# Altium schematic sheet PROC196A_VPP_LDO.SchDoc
size 431 x 279 mm; Date: Not shown in title block; ApprovedBy: Not shown in title block; CheckedBy: Not shown in title block; Author: Not shown in title block; CompanyName: Not shown in title block; Engineer: Not shown in title block; Organization: Not shown in title block; Address1: Not shown in title block; Address2: Not shown in title block; Address3: Not shown in title block; Address4: Not shown in title block; DocumentNumber: 10; Revision: Use project parameter SCH_Rev; SheetNumber: 10; SheetTotal: 25; PageSetup: Record=PageOptions¦CenterHorizontal=True¦CenterVertical=True¦PrintScale=1.00¦XCorrection=1.00¦YCorrection=1.00¦PrintKind=0¦BorderSize=5000000¦LeftOffset=0¦BottomOffset=0¦Orientation=2¦PaperLength=1000¦PaperWidth=1000¦Scale=100¦PaperSource=15¦PrintQuality=600¦MediaType=1¦DitherType=10¦PaperKind=Letter¦PrintScaleMode=1
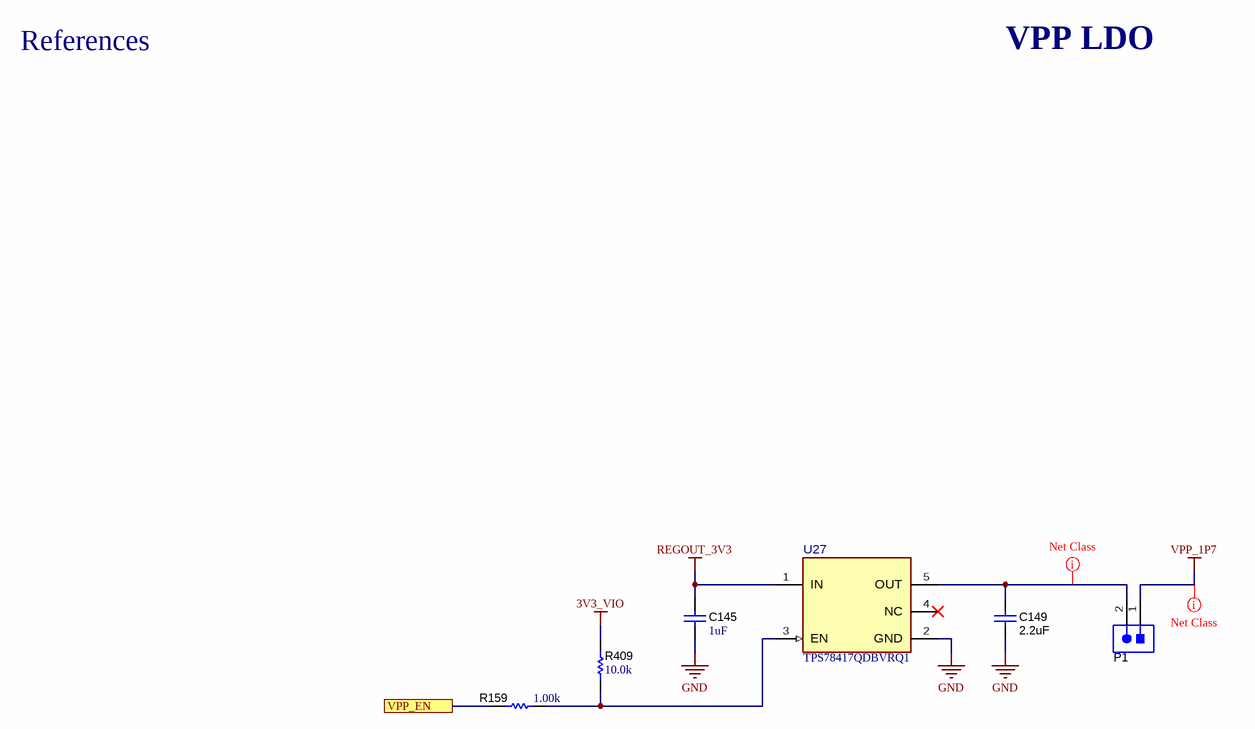
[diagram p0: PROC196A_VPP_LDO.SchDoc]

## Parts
C145  ValueDisplayed: 1uF  [0603L]  (hidden comment: GCM188R71C105KA64D)
C149  ValueDisplayed: 2.2uF  [0603L]  (hidden comment: GCM188R70J225KE22D)
P1  TSW-102-07-G-S  [TSW-102-07-G-S]  (value not drawn)
R159  ValueDisplayed: 1.00k  [0402L]  (hidden comment: CRCW04021K00FKED)
R409  ValueDisplayed: 10.0k  [0402L]  (hidden comment: CRCW040210K0FKED)
U27  TPS78417QDBVRQ1  [DBV0005A-MFG]

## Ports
VPP_EN

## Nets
3V3_VIO: R409.2
GND: C145.2 C149.1 U27.2(GND)
REGOUT_3V3: C145.1 U27.1(IN)
VPP_1P7: P1.1
VPP_EN: R159.1 ; port VPP_EN
NetC149_2: C149.2 P1.2 U27.5(OUT)
NetR159_2: R159.2 R409.1 U27.3(EN)

Not connected (* = marked no-connect by the designer): U27 4(NC)*

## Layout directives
net class PWR: NetC149_2, VPP_1P7

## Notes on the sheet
- References
- VPP LDO

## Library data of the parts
C145 = CMP-0007136-5: CAP, CERM, 1 uF, 16 V, +/- 10%, X7R, AEC-Q200 Grade 1, 0603; Manufacturer: MuRata; TaMin_C: -55°C; Polarized: N; SizeAreaWB_mm2: 4.68; Value1: Unknown; U/M: EA; Value: 1uF; TaMax_C: 125°C; SizeZ_mm: 1; SizeX_mm: 1.6; SizeY_mm: 0.8; Cap_Case: 0603; Value2: 16V; SizeArea_mm2: 1.28; CompType: Capacitor; AEC Qualified: Y; Cap_F: 1µF; AEC Category: Q200
C149 = CMP-0007134-5: CAP, CERM, 2.2 uF, 6.3 V, +/- 10%, X7R, AEC-Q200 Grade 1, 0603; Manufacturer: MuRata; TaMin_C: -55°C; Polarized: N; SizeAreaWB_mm2: 4.68; Value1: Unknown; U/M: EA; Value: 2.2uF; TaMax_C: 125°C; SizeZ_mm: 1; SizeX_mm: 1.6; SizeY_mm: 0.8; Cap_Case: 0603; Value2: 6.3V; SizeArea_mm2: 1.28; AEC Qualified: Y; Cap_F: 2.2µF; AEC Category: Q200
P1 = CMP-0075405-3: Header, 100mil, 2x1, Gold, TH; Manufacturer: Samtec; Pitch_mm: 2.54; Cert_VDE: N; Gender: Male; Cert_CSA: Y; Voltage_V: 550V; Green_REACh: Passed; Current_A: 6.3A; Green_Lifecycle: Active; Row_Count: 1
R159 = CMP-0026071-3: RES, 1.00 k, 1%, 0.063 W, AEC-Q200 Grade 0, 0402; Manufacturer: Vishay-Dale; Power_W: 63mW; TempCo: 100 ppm/C; Value_Code: 1k00; Value: 1.00k; EIA_Code: E96; Res_ohm: 1k; SizeX_mm: 1; SizeY_mm: 0.5; SizeZ_mm: 0.6; Value2: 0.063W; AEC Qualified: Y; VDC_V: 50V; AEC Category: Q200; AEC Grade: 0
R409 = CMP-0025958-3: RES, 10.0 k, 1%, 0.063 W, AEC-Q200 Grade 0, 0402; Manufacturer: Vishay-Dale; Power_W: 63mW; TempCo: 100 ppm/C; Value_Code: 10k0; Value: 10.0k; EIA_Code: E96; Res_ohm: 10k; SizeX_mm: 1; SizeY_mm: 0.5; SizeZ_mm: 0.6; Value2: 0.063W; AEC Qualified: Y; VDC_V: 50V; AEC Category: Q200; AEC Grade: 0
U27 = CMP-0092338-1: Linear Voltage Regulator IC Positive Fixed Output 300mA SOT-23-5; Manufacturer: Texas Instruments; TaMin_C: -40°C; Output Voltage: 1.7V; Standoff Height: 0mm; SizeZ_mm: 1.45mm; TaMax_C: +125°C; Accuracy Percentage: 0.5%; AEC Grade: Grade 1; Number Of Outputs: 1; AEC Qualified: Yes; Max Supply Voltage: 6V; Dropout Voltage: 900mV; Nominal Supply Current: 0.033mA; Min Supply Voltage: 1.65V; TJmax_C: +150°C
